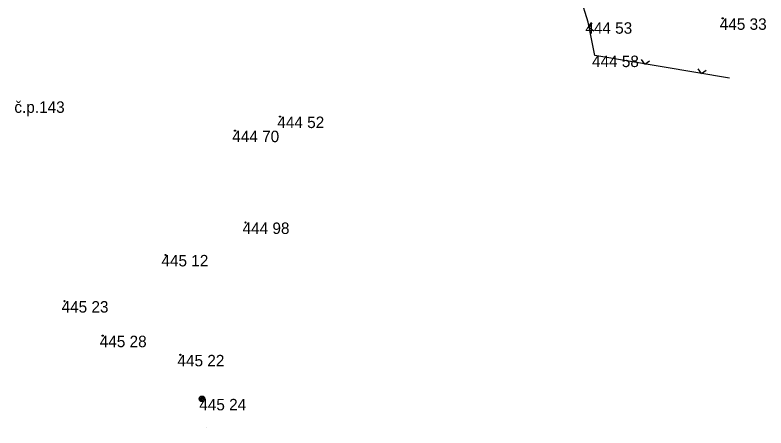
# Model space of a CAD drawing. Extents: x -554123 to -553118, y -1076825 to -1073672.
# Drawn here: x -553927.3 to -553861.8, y -1074695.7 to -1074659.7 of the extents above; entities that cross this region are included whole.
import ezdxf

# ---------------------------------------------------------------- set-up
doc = ezdxf.new("R2010")
doc.units = 0
for name, color, linetype in [('1', 7, 'Continuous'), ('12', 7, 'Continuous'), ('20', 7, 'Continuous'), ('54', 7, 'Continuous'), ('6', 7, 'Continuous')]:
    doc.layers.add(name, color=color, linetype=linetype)

# ---------------------------------------------------------------- blocks, each defined once
blk = doc.blocks.new('POINT_DISPLAY')
blk.add_line((0, 0), (0, 0))
blk = doc.blocks.new('T')
at = {"layer": '6'}
blk.add_circle((0, 0), 0.05, dxfattribs=at)
blk = doc.blocks.new('SLDP')
at = {"layer": '20'}
for radius in [0.25, 0.158, 0.05]:
    blk.add_circle((0, 0), radius, dxfattribs=at)

msp = doc.modelspace()

# ---------------------------------------------------------------- linework, layer by layer
at = {"layer": '12'}
for p, q in [((-553877.32, -1074660.3), (-553879, -1074654.7)), ((-553876.74, -1074663.21), (-553877.32, -1074660.3)), ((-553877.229, -1074660.758), (-553876.951, -1074660.342)), ((-553877.229, -1074660.758), (-553876.812, -1074661.036)), ((-553864.97, -1074665.18), (-553876.74, -1074663.21)), ((-553872.367, -1074663.942), (-553872.658, -1074663.534)), ((-553872.367, -1074663.942), (-553871.96, -1074663.651)), ((-553867.436, -1074664.767), (-553867.726, -1074664.36)), ((-553867.436, -1074664.767), (-553867.028, -1074664.477))]:
    msp.add_line(p, q, dxfattribs=at)

# ---------------------------------------------------------------- block references
at = {"layer": '1'}
for p in [(-553865.58, -1074659.96), (-553877.32, -1074660.3), (-553876.74, -1074663.21), (-553904.19, -1074668.53), (-553908.12, -1074669.76), (-553907.21, -1074677.77), (-553914.18, -1074680.6), (-553923, -1074684.63), (-553919.67, -1074687.65), (-553912.89, -1074689.32), (-553911, -1074693.16), (-553910.63, -1074695.7)]:
    msp.add_blockref('POINT_DISPLAY', p, dxfattribs=at)
at = {"layer": '20'}
msp.add_blockref('SLDP', (-553911, -1074693.16), dxfattribs=at)
at = {"layer": '6'}
for p in [(-553865.58, -1074659.96), (-553904.19, -1074668.53), (-553908.12, -1074669.76), (-553907.21, -1074677.77), (-553914.18, -1074680.6), (-553923, -1074684.63), (-553919.67, -1074687.65), (-553912.89, -1074689.32)]:
    msp.add_blockref('T', p, dxfattribs=at)

# ---------------------------------------------------------------- texts
at = {"layer": '54'}
msp.add_text('č.p.143', height=1, dxfattribs=at).set_placement((-553927.37, -1074668.203))
at = {"layer": '6'}
for s, p in [('445 33 ', (-553865.83, -1074660.96)), ('444 53 ', (-553877.558, -1074661.3)), ('444 58 ', (-553876.978, -1074664.21)), ('444 52 ', (-553904.428, -1074669.53)), ('444 70 ', (-553908.358, -1074670.76)), ('444 98 ', (-553907.46, -1074678.77)), ('445 12 ', (-553914.539, -1074681.6)), ('445 23 ', (-553923.25, -1074685.63)), ('445 28 ', (-553919.92, -1074688.65)), ('445 22 ', (-553913.14, -1074690.32)), ('445 24 ', (-553911.238, -1074694.16))]:
    msp.add_text(s, height=1, dxfattribs=at).set_placement(p)

doc.saveas('drawing.dxf')
